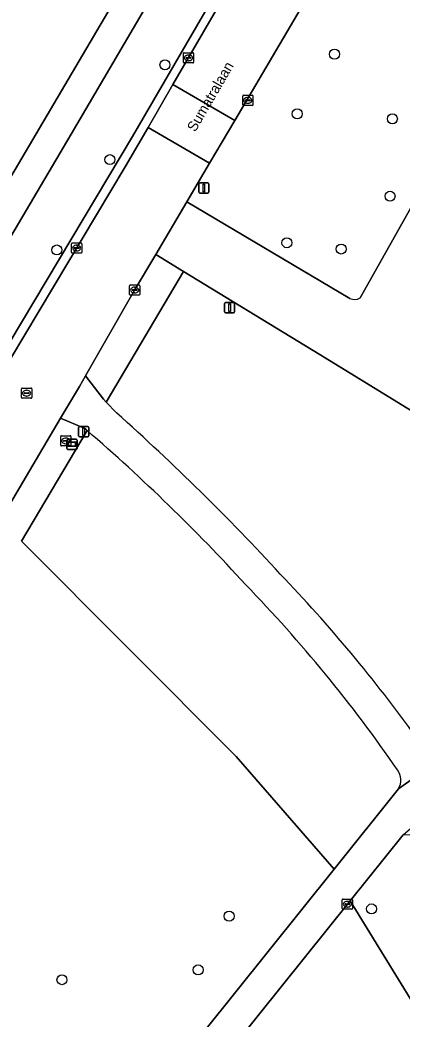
# Model space of a CAD drawing. Extents: x 162417 to 163722, y 384268 to 385417.
# Drawn here: x 162563 to 162600.4, y 384792.3 to 384890.1 of the extents above; entities that cross this region are included whole.
import ezdxf

# ---------------------------------------------------------------- set-up
doc = ezdxf.new("R2010")
doc.units = 0
for name, color, linetype in [('IMGEO_Berm_groen', 7, 'Continuous'), ('IMGEO_Boom', 7, 'Continuous'), ('IMGEO_Brandkraan', 7, 'Continuous'), ('IMGEO_Fietspad_gesloten', 7, 'Continuous'), ('IMGEO_Groenvoorziening', 7, 'Continuous'), ('IMGEO_Kolk', 7, 'Continuous'), ('IMGEO_Lichtmast', 7, 'Continuous'), ('IMGEO_Loofbos', 7, 'Continuous'), ('IMGEO_Openbare_ruimte_label', 7, 'Continuous'), ('IMGEO_Parkeervlak_gesloten', 7, 'Continuous'), ('IMGEO_Rijbaan_lokaal_open', 7, 'Continuous'), ('IMGEO_Rioolput', 7, 'Continuous'), ('IMGEO_Verkeersbordpaal', 7, 'Continuous'), ('IMGEO_Verkeerseiland_open', 7, 'Continuous'), ('IMGEO_Verklikker', 7, 'Continuous'), ('IMGEO_Voetpad_gesloten', 7, 'Continuous')]:
    doc.layers.add(name, color=color, linetype=linetype)

msp = doc.modelspace()

# ---------------------------------------------------------------- linework, layer by layer
at = {"layer": 'IMGEO_Berm_groen'}
for points in [[(162646.158, 385011.686), (162636.511, 384995.272), (162626.239, 384977.745), (162605.301, 384942.481), (162574.943, 384890.8), (162567.991, 384878.959), (162546.279, 384842.21), (162538.301, 384828.127)], [(162512.784, 384784.469), (162517.731, 384790.829), (162522.347, 384797.449), (162531.41, 384811.598), (162533.25, 384810.499), (162574.003, 384878.733), (162603.443, 384929.38), (162645.063, 385000)]]:
    msp.add_lwpolyline(points, dxfattribs=at)
at = {"layer": 'IMGEO_Boom'}
for centre in [(162593.756, 384886.796), (162577.174, 384885.747), (162590.108, 384880.956), (162599.418, 384880.47), (162571.785, 384876.48), (162599.186, 384872.902), (162589.1, 384868.347), (162566.6, 384867.643), (162594.409, 384867.736), (162597.381, 384803.204), (162583.448, 384802.497), (162580.423, 384797.242), (162567.1, 384796.281)]:
    msp.add_circle(centre, 0.489, dxfattribs=at)
at = {"layer": 'IMGEO_Brandkraan'}
for p, q in [((162566.977, 384848.551), (162566.977, 384849.403)), ((162567.052, 384849.477), (162567.904, 384849.477)), ((162567.465, 384849.257), (162567.49, 384849.257)), ((162567.978, 384849.403), (162567.978, 384848.551)), ((162567.904, 384848.477), (162567.052, 384848.477)), ((162567.236, 384848.971), (162567.236, 384848.983)), ((162567.674, 384848.934), (162567.276, 384848.934)), ((162567.279, 384849.02), (162567.677, 384849.02)), ((162567.488, 384848.697), (162567.463, 384848.697)), ((162567.72, 384848.983), (162567.72, 384848.971))]:
    msp.add_line(p, q, dxfattribs=at)
for points in [[(162566.977, 384848.551), (162566.977, 384849.403)], [(162567.052, 384849.477), (162567.904, 384849.477)], [(162567.978, 384849.403), (162567.978, 384848.551)], [(162567.904, 384848.477), (162567.052, 384848.477)]]:
    msp.add_lwpolyline(points, dxfattribs=at)
for centre, radius, start, end in [((162567.054, 384849.401), 0.0765, 91.55205, 178.44795), ((162567.054, 384849.401), 0.0765, 91.55205, 178.44795), ((162567.902, 384849.401), 0.0765, 1.55205, 88.44795), ((162567.902, 384849.401), 0.0765, 1.55205, 88.44795), ((162567.054, 384848.553), 0.0765, 181.55205, 268.44795), ((162567.054, 384848.553), 0.0765, 181.55205, 268.44795), ((162567.276, 384848.98), 0.0403, 85.87752, 175.75265), ((162567.273, 384848.97), 0.0366, 178.93798, 274.71019), ((162567.677, 384848.977), 0.043, 264.86636, 352.45326), ((162567.681, 384848.982), 0.0386, 1.73085, 96.63898), ((162567.902, 384848.553), 0.0765, 271.55205, 358.44795), ((162567.902, 384848.553), 0.0765, 271.55205, 358.44795)]:
    msp.add_arc(centre, radius, start, end, dxfattribs=at)
for centre, major_axis, ratio, start_param, end_param in [((162567.464, 384848.977), (-0.387, 0.002), 0.722429, 4.712389, 7.853982), ((162567.489, 384848.977), (-0.39, 0.002), 0.717154, 1.570796, 4.712389)]:
    msp.add_ellipse(centre, major_axis=major_axis, ratio=ratio, start_param=start_param, end_param=end_param, dxfattribs=at)
at = {"layer": 'IMGEO_Fietspad_gesloten'}
for points in [[(162538.301, 384828.127), (162546.279, 384842.21), (162567.991, 384878.959), (162574.943, 384890.8), (162605.301, 384942.481), (162626.239, 384977.745), (162636.511, 384995.272), (162646.158, 385011.686), (162665.162, 385043.815), (162688.11, 385082.922), (162698.612, 385100.627), (162708.059, 385116.686), (162716.824, 385131.415), (162722.948, 385142.12), (162732.602, 385158.264), (162737.703, 385167.304), (162744.274, 385178.198), (162747.814, 385184.015), (162751.837, 385189.593), (162755.758, 385194.058), (162761.272, 385200.676), (162764.186, 385204.086), (162767.106, 385207.275)], [(162728.189, 385156.751), (162639.731, 385006.611), (162638.556, 385004.617), (162637.018, 385002.006), (162635.965, 385000.219), (162635.836, 385000), (162541.367, 384839.659), (162536.789, 384831.846)]]:
    msp.add_lwpolyline(points, dxfattribs=at)
at = {"layer": 'IMGEO_Groenvoorziening'}
for points in [[(162536.789, 384831.846), (162541.367, 384839.659), (162635.836, 385000)], [(162633.966, 384921.515), (162627.253, 384920.845), (162606.724, 384919.159), (162596.142, 384900.925), (162583.998, 384880.314), (162581.541, 384876.144), (162579.3, 384872.341), (162595.252, 384862.905)], [(162596.252, 384862.955), (162608.361, 384884.447), (162624.176, 384912.71), (162630.141, 384909.345), (162631.465, 384909.747), (162631.987, 384910.232), (162636.105, 384917.629)], [(162593.733, 384807.099), (162584.151, 384818.116), (162563.152, 384839.163), (162569.554, 384849.987), (162569.417, 384850.105), (162569.279, 384850.223), (162566.97, 384851.211), (162540.368, 384806.125), (162542.942, 384804.552), (162541.302, 384801.661), (162539.637, 384798.807), (162533.671, 384788.344), (162529.98, 384781.104), (162527.976, 384776.852), (162526.899, 384773.575), (162525.814, 384770.003)], [(162604.297, 384810.402), (162600.477, 384810.447), (162595.297, 384803.992), (162606.136, 384786.338), (162615.926, 384792.421)], [(162532.879, 384755.269), (162541.11, 384750), (162545.602, 384747.124), (162593.733, 384807.099)], [(162619.678, 384785.416), (162615.926, 384792.421), (162606.136, 384786.338), (162595.297, 384803.992), (162568.435, 384770.521), (162570.041, 384769.255), (162570.101, 384769.331), (162571.485, 384768.241), (162570.384, 384766.843), (162569, 384767.934), (162569.063, 384768.014), (162567.447, 384769.289), (162548.211, 384745.32), (162564.266, 384734.123)]]:
    msp.add_lwpolyline(points, dxfattribs=at)
msp.add_lwpolyline([(162578.998, 384865.545), (162576.291, 384867.199), (162574.209, 384863.722), (162569.407, 384855.341), (162571.149, 384853.057), (162571.438, 384852.752)], close=True, dxfattribs=at)
msp.add_arc((162595.705, 384863.868), 1.064, 244.7926, 300.93221, dxfattribs=at)
at = {"layer": 'IMGEO_Kolk'}
for p, q in [((162578.972, 384886.005), (162578.972, 384886.857)), ((162579.047, 384886.931), (162579.899, 384886.931)), ((162579.231, 384886.425), (162579.231, 384886.437)), ((162579.669, 384886.388), (162579.271, 384886.388)), ((162579.274, 384886.474), (162579.672, 384886.474)), ((162579.46, 384886.711), (162579.485, 384886.711)), ((162579.715, 384886.437), (162579.715, 384886.425)), ((162579.973, 384886.857), (162579.973, 384886.005)), ((162579.899, 384885.931), (162579.047, 384885.931)), ((162579.483, 384886.151), (162579.458, 384886.151)), ((162584.783, 384881.844), (162584.783, 384882.696)), ((162584.858, 384882.77), (162585.71, 384882.77)), ((162585.271, 384882.55), (162585.296, 384882.55)), ((162585.784, 384882.696), (162585.784, 384881.844)), ((162585.71, 384881.77), (162584.858, 384881.77)), ((162585.042, 384882.264), (162585.042, 384882.276)), ((162585.48, 384882.227), (162585.082, 384882.227)), ((162585.085, 384882.313), (162585.483, 384882.313)), ((162585.294, 384881.99), (162585.269, 384881.99)), ((162585.526, 384882.276), (162585.526, 384882.264)), ((162568.037, 384867.406), (162568.037, 384868.258)), ((162568.112, 384868.332), (162568.964, 384868.332)), ((162568.296, 384867.826), (162568.296, 384867.838)), ((162568.734, 384867.789), (162568.336, 384867.789)), ((162568.339, 384867.875), (162568.737, 384867.875)), ((162568.525, 384868.112), (162568.55, 384868.112)), ((162568.78, 384867.838), (162568.78, 384867.826)), ((162569.038, 384868.258), (162569.038, 384867.406)), ((162568.964, 384867.332), (162568.112, 384867.332)), ((162568.548, 384867.552), (162568.523, 384867.552)), ((162573.713, 384863.296), (162573.713, 384864.148)), ((162573.788, 384864.222), (162574.64, 384864.222)), ((162574.201, 384864.002), (162574.226, 384864.002)), ((162574.714, 384864.148), (162574.714, 384863.296)), ((162574.64, 384863.222), (162573.788, 384863.222)), ((162573.972, 384863.716), (162573.972, 384863.728)), ((162574.41, 384863.679), (162574.012, 384863.679)), ((162574.015, 384863.765), (162574.413, 384863.765)), ((162574.224, 384863.442), (162574.199, 384863.442)), ((162574.456, 384863.728), (162574.456, 384863.716)), ((162594.515, 384803.241), (162594.515, 384804.093)), ((162594.59, 384804.167), (162595.442, 384804.167)), ((162594.774, 384803.661), (162594.774, 384803.673)), ((162595.212, 384803.624), (162594.814, 384803.624)), ((162594.817, 384803.71), (162595.215, 384803.71)), ((162595.026, 384803.387), (162595.001, 384803.387)), ((162595.003, 384803.947), (162595.028, 384803.947)), ((162595.258, 384803.673), (162595.258, 384803.661)), ((162595.516, 384804.093), (162595.516, 384803.241)), ((162595.442, 384803.167), (162594.59, 384803.167))]:
    msp.add_line(p, q, dxfattribs=at)
for points in [[(162578.972, 384886.005), (162578.972, 384886.857)], [(162579.047, 384886.931), (162579.899, 384886.931)], [(162579.973, 384886.857), (162579.973, 384886.005)], [(162579.899, 384885.931), (162579.047, 384885.931)], [(162584.783, 384881.844), (162584.783, 384882.696)], [(162584.858, 384882.77), (162585.71, 384882.77)], [(162585.784, 384882.696), (162585.784, 384881.844)], [(162585.71, 384881.77), (162584.858, 384881.77)], [(162568.037, 384867.406), (162568.037, 384868.258)], [(162568.112, 384868.332), (162568.964, 384868.332)], [(162569.038, 384868.258), (162569.038, 384867.406)], [(162568.964, 384867.332), (162568.112, 384867.332)], [(162573.713, 384863.296), (162573.713, 384864.148)], [(162573.788, 384864.222), (162574.64, 384864.222)], [(162574.714, 384864.148), (162574.714, 384863.296)], [(162574.64, 384863.222), (162573.788, 384863.222)], [(162594.515, 384803.241), (162594.515, 384804.093)], [(162594.59, 384804.167), (162595.442, 384804.167)], [(162595.516, 384804.093), (162595.516, 384803.241)], [(162595.442, 384803.167), (162594.59, 384803.167)]]:
    msp.add_lwpolyline(points, dxfattribs=at)
for centre, radius, start, end in [((162579.049, 384886.855), 0.0765, 91.55205, 178.44795), ((162579.049, 384886.855), 0.0765, 91.55205, 178.44795), ((162579.271, 384886.434), 0.0403, 85.87752, 175.75265), ((162579.268, 384886.424), 0.0366, 178.93798, 274.71019), ((162579.672, 384886.431), 0.043, 264.86636, 352.45326), ((162579.676, 384886.436), 0.0386, 1.73085, 96.63898), ((162579.897, 384886.855), 0.0765, 1.55205, 88.44795), ((162579.897, 384886.855), 0.0765, 1.55205, 88.44795), ((162579.049, 384886.007), 0.0765, 181.55205, 268.44795), ((162579.049, 384886.007), 0.0765, 181.55205, 268.44795), ((162579.897, 384886.007), 0.0765, 271.55205, 358.44795), ((162579.897, 384886.007), 0.0765, 271.55205, 358.44795), ((162584.86, 384882.694), 0.0765, 91.55205, 178.44795), ((162584.86, 384882.694), 0.0765, 91.55205, 178.44795), ((162585.708, 384882.694), 0.0765, 1.55205, 88.44795), ((162585.708, 384882.694), 0.0765, 1.55205, 88.44795), ((162584.86, 384881.846), 0.0765, 181.55205, 268.44795), ((162584.86, 384881.846), 0.0765, 181.55205, 268.44795), ((162585.082, 384882.273), 0.0403, 85.87752, 175.75265), ((162585.079, 384882.263), 0.0366, 178.93798, 274.71019), ((162585.483, 384882.27), 0.043, 264.86636, 352.45326), ((162585.487, 384882.275), 0.0386, 1.73085, 96.63898), ((162585.708, 384881.846), 0.0765, 271.55205, 358.44795), ((162585.708, 384881.846), 0.0765, 271.55205, 358.44795), ((162568.114, 384868.256), 0.0765, 91.55205, 178.44795), ((162568.114, 384868.256), 0.0765, 91.55205, 178.44795), ((162568.336, 384867.835), 0.0403, 85.87752, 175.75265), ((162568.333, 384867.825), 0.0366, 178.93798, 274.71019), ((162568.737, 384867.832), 0.043, 264.86636, 352.45326), ((162568.741, 384867.837), 0.0386, 1.73085, 96.63898), ((162568.962, 384868.256), 0.0765, 1.55205, 88.44795), ((162568.962, 384868.256), 0.0765, 1.55205, 88.44795), ((162568.114, 384867.408), 0.0765, 181.55205, 268.44795), ((162568.114, 384867.408), 0.0765, 181.55205, 268.44795), ((162568.962, 384867.408), 0.0765, 271.55205, 358.44795), ((162568.962, 384867.408), 0.0765, 271.55205, 358.44795), ((162573.79, 384864.146), 0.0765, 91.55205, 178.44795), ((162573.79, 384864.146), 0.0765, 91.55205, 178.44795), ((162574.638, 384864.146), 0.0765, 1.55205, 88.44795), ((162574.638, 384864.146), 0.0765, 1.55205, 88.44795), ((162573.79, 384863.298), 0.0765, 181.55205, 268.44795), ((162573.79, 384863.298), 0.0765, 181.55205, 268.44795), ((162574.012, 384863.725), 0.0403, 85.87752, 175.75265), ((162574.009, 384863.715), 0.0366, 178.93798, 274.71019), ((162574.413, 384863.722), 0.043, 264.86636, 352.45326), ((162574.417, 384863.727), 0.0386, 1.73085, 96.63898), ((162574.638, 384863.298), 0.0765, 271.55205, 358.44795), ((162574.638, 384863.298), 0.0765, 271.55205, 358.44795), ((162594.592, 384804.091), 0.0765, 91.55205, 178.44795), ((162594.592, 384804.091), 0.0765, 91.55205, 178.44795), ((162594.814, 384803.67), 0.0403, 85.87752, 175.75265), ((162594.811, 384803.66), 0.0366, 178.93798, 274.71019), ((162595.215, 384803.667), 0.043, 264.86636, 352.45326), ((162595.219, 384803.672), 0.0386, 1.73085, 96.63898), ((162595.44, 384804.091), 0.0765, 1.55205, 88.44795), ((162595.44, 384804.091), 0.0765, 1.55205, 88.44795), ((162594.592, 384803.243), 0.0765, 181.55205, 268.44795), ((162594.592, 384803.243), 0.0765, 181.55205, 268.44795), ((162595.44, 384803.243), 0.0765, 271.55205, 358.44795), ((162595.44, 384803.243), 0.0765, 271.55205, 358.44795)]:
    msp.add_arc(centre, radius, start, end, dxfattribs=at)
for centre, major_axis, ratio, start_param, end_param in [((162579.459, 384886.431), (-0.387, 0.002), 0.722429, 4.712389, 7.853982), ((162579.484, 384886.431), (-0.39, 0.002), 0.717154, 1.570796, 4.712389), ((162585.27, 384882.27), (-0.387, 0.002), 0.722429, 4.712389, 7.853982), ((162585.295, 384882.27), (-0.39, 0.002), 0.717154, 1.570796, 4.712389), ((162568.524, 384867.832), (-0.387, 0.002), 0.722429, 4.712389, 7.853982), ((162568.549, 384867.832), (-0.39, 0.002), 0.717154, 1.570796, 4.712389), ((162574.2, 384863.722), (-0.387, 0.002), 0.722429, 4.712389, 7.853982), ((162574.225, 384863.722), (-0.39, 0.002), 0.717154, 1.570796, 4.712389), ((162595.002, 384803.667), (-0.387, 0.002), 0.722429, 4.712389, 7.853982), ((162595.027, 384803.667), (-0.39, 0.002), 0.717154, 1.570796, 4.712389)]:
    msp.add_ellipse(centre, major_axis=major_axis, ratio=ratio, start_param=start_param, end_param=end_param, dxfattribs=at)
at = {"layer": 'IMGEO_Lichtmast'}
for p, q in [((162580.479, 384873.302), (162580.479, 384874.102)), ((162580.479, 384874.102), (162580.479, 384873.302)), ((162580.579, 384874.202), (162581.369, 384874.202)), ((162581.369, 384874.202), (162580.579, 384874.202)), ((162581.469, 384874.102), (162581.469, 384873.302)), ((162581.469, 384873.302), (162581.469, 384874.102)), ((162581.369, 384873.202), (162580.579, 384873.202)), ((162580.579, 384873.202), (162581.369, 384873.202))]:
    msp.add_line(p, q, dxfattribs=at)
msp.add_lwpolyline([(162580.899, 384874.077), (162581.049, 384874.077), (162581.049, 384873.327), (162580.899, 384873.327), (162580.899, 384874.077)], dxfattribs=at)
for centre, start, end in [((162580.579, 384874.102), 90, 180), ((162580.579, 384874.102), 90, 180), ((162581.369, 384874.102), 0, 90), ((162581.369, 384874.102), 360, 90), ((162580.579, 384873.302), 180, 270), ((162580.579, 384873.302), 180, 270), ((162581.369, 384873.302), 270, 0), ((162581.369, 384873.302), 270, 0)]:
    msp.add_arc(centre, 0.1, start, end, dxfattribs=at)
at = {"layer": 'IMGEO_Loofbos'}
for points in [[(162609.827, 384847.286), (162609.567, 384846.838), (162596.309, 384854.964), (162592.241, 384857.45), (162578.998, 384865.545), (162571.438, 384852.752), (162572.419, 384851.714)], [(162569.554, 384849.987), (162563.152, 384839.163), (162584.151, 384818.116), (162593.733, 384807.099), (162600.029, 384814.944)]]:
    msp.add_lwpolyline(points, dxfattribs=at)
for centre, radius, start, end in [((162426.197, 384687.011), 220.245, 42.54989, 48.40153), ((162451.895, 384713.407), 180.271, 42.38212, 49.25613), ((162483.277, 384734.796), 145.921, 35.72297, 43.88394), ((162482.506, 384735.63), 142.743, 34.6554, 44.07578), ((162598.455, 384815.785), 1.784, 331.86516, 34.61424)]:
    msp.add_arc(centre, radius, start, end, dxfattribs=at)
at = {"layer": 'IMGEO_Parkeervlak_gesloten'}
for points in [[(162642.404, 384902.325), (162636.868, 384905.565), (162630.141, 384909.345), (162624.176, 384912.71), (162608.361, 384884.447), (162596.252, 384862.955)], [(162595.252, 384862.905), (162579.3, 384872.341), (162576.291, 384867.199), (162578.998, 384865.545), (162592.241, 384857.45), (162596.309, 384854.964), (162609.567, 384846.838), (162609.827, 384847.286), (162612.071, 384851.147), (162612.197, 384851.361), (162625.393, 384873.785), (162642.404, 384902.325)]]:
    msp.add_lwpolyline(points, dxfattribs=at)
msp.add_arc((162595.705, 384863.868), 1.064, 244.7926, 300.93221, dxfattribs=at)
at = {"layer": 'IMGEO_Rijbaan_lokaal_open'}
for points in [[(162577.959, 384883.818), (162583.998, 384880.314), (162596.142, 384900.925), (162606.724, 384919.159), (162611.145, 384926.587), (162654.361, 385000), (162655.133, 385001.311), (162659.828, 385009.341), (162691.301, 385062.57), (162692.946, 385065.327), (162693.28, 385065.893), (162687.012, 385069.599), (162646.005, 385000), (162607.006, 384933.97), (162586.721, 384898.921)], [(162575.53, 384879.632), (162581.541, 384876.144), (162583.998, 384880.314), (162577.959, 384883.818)]]:
    msp.add_lwpolyline(points, close=True, dxfattribs=at)
msp.add_lwpolyline([(162529.821, 384787.499), (162530.911, 384789.535), (162534.987, 384797.022), (162540.368, 384806.125), (162566.97, 384851.211), (162568.815, 384854.307), (162569.407, 384855.341), (162574.209, 384863.722), (162576.291, 384867.199), (162579.3, 384872.341), (162581.541, 384876.144), (162575.53, 384879.632), (162573.285, 384875.763), (162533.977, 384810.065), (162532.771, 384808.049), (162523.657, 384794.437), (162522.365, 384792.536), (162521.094, 384790.707), (162519.826, 384788.918), (162513.62, 384780.863)], dxfattribs=at)
at = {"layer": 'IMGEO_Rioolput'}
for p, q in [((162563.214, 384854.142), (162564.066, 384854.142)), ((162563.139, 384853.216), (162563.139, 384854.068)), ((162564.066, 384853.142), (162563.214, 384853.142)), ((162563.398, 384853.636), (162563.398, 384853.648)), ((162563.836, 384853.599), (162563.438, 384853.599)), ((162563.441, 384853.685), (162563.839, 384853.685)), ((162563.65, 384853.362), (162563.625, 384853.362)), ((162563.627, 384853.922), (162563.652, 384853.922)), ((162563.882, 384853.648), (162563.882, 384853.636)), ((162564.14, 384854.068), (162564.14, 384853.216))]:
    msp.add_line(p, q, dxfattribs=at)
for points in [[(162563.214, 384854.142), (162564.066, 384854.142)], [(162563.139, 384853.216), (162563.139, 384854.068)], [(162564.066, 384853.142), (162563.214, 384853.142)], [(162564.14, 384854.068), (162564.14, 384853.216)]]:
    msp.add_lwpolyline(points, dxfattribs=at)
for centre, radius, start, end in [((162563.216, 384854.066), 0.0765, 91.55205, 178.44795), ((162563.216, 384854.066), 0.0765, 91.55205, 178.44795), ((162564.064, 384854.066), 0.0765, 1.55205, 88.44795), ((162564.064, 384854.066), 0.0765, 1.55205, 88.44795), ((162563.216, 384853.218), 0.0765, 181.55205, 268.44795), ((162563.216, 384853.218), 0.0765, 181.55205, 268.44795), ((162563.438, 384853.645), 0.0403, 85.87752, 175.75265), ((162563.435, 384853.635), 0.0366, 178.93798, 274.71019), ((162563.839, 384853.642), 0.043, 264.86636, 352.45326), ((162563.843, 384853.647), 0.0386, 1.73085, 96.63898), ((162564.064, 384853.218), 0.0765, 271.55205, 358.44795), ((162564.064, 384853.218), 0.0765, 271.55205, 358.44795)]:
    msp.add_arc(centre, radius, start, end, dxfattribs=at)
for centre, major_axis, ratio, start_param, end_param in [((162563.626, 384853.642), (-0.387, 0.002), 0.722429, 4.712389, 7.853982), ((162563.651, 384853.642), (-0.39, 0.002), 0.717154, 1.570796, 4.712389)]:
    msp.add_ellipse(centre, major_axis=major_axis, ratio=ratio, start_param=start_param, end_param=end_param, dxfattribs=at)
at = {"layer": 'IMGEO_Verkeersbordpaal'}
for p, q in [((162583, 384861.606), (162583, 384862.406)), ((162583, 384862.406), (162583, 384861.606)), ((162583.1, 384862.506), (162583.89, 384862.506)), ((162583.89, 384862.506), (162583.1, 384862.506)), ((162583.99, 384862.406), (162583.99, 384861.606)), ((162583.99, 384861.606), (162583.99, 384862.406)), ((162583.89, 384861.506), (162583.1, 384861.506)), ((162583.1, 384861.506), (162583.89, 384861.506)), ((162568.727, 384849.484), (162568.727, 384850.284)), ((162568.727, 384850.284), (162568.727, 384849.484)), ((162568.827, 384850.384), (162569.617, 384850.384)), ((162569.617, 384850.384), (162568.827, 384850.384)), ((162569.717, 384850.284), (162569.717, 384849.484)), ((162569.717, 384849.484), (162569.717, 384850.284)), ((162569.617, 384849.384), (162568.827, 384849.384)), ((162568.827, 384849.384), (162569.617, 384849.384))]:
    msp.add_line(p, q, dxfattribs=at)
for points in [[(162583.42, 384862.381), (162583.57, 384862.381), (162583.57, 384861.631), (162583.42, 384861.631), (162583.42, 384862.381)], [(162569.147, 384850.259), (162569.297, 384850.259), (162569.297, 384849.509), (162569.147, 384849.509), (162569.147, 384850.259)]]:
    msp.add_lwpolyline(points, dxfattribs=at)
for centre, start, end in [((162583.1, 384862.406), 90, 180), ((162583.1, 384862.406), 90, 180), ((162583.89, 384862.406), 0, 90), ((162583.89, 384862.406), 360, 90), ((162583.1, 384861.606), 180, 270), ((162583.1, 384861.606), 180, 270), ((162583.89, 384861.606), 270, 0), ((162583.89, 384861.606), 270, 0), ((162568.827, 384850.284), 90, 180), ((162568.827, 384850.284), 90, 180), ((162569.617, 384850.284), 0, 90), ((162569.617, 384850.284), 360, 90), ((162568.827, 384849.484), 180, 270), ((162568.827, 384849.484), 180, 270), ((162569.617, 384849.484), 270, 0), ((162569.617, 384849.484), 270, 0)]:
    msp.add_arc(centre, 0.1, start, end, dxfattribs=at)
at = {"layer": 'IMGEO_Verkeerseiland_open'}
msp.add_lwpolyline([(162767.106, 385207.275), (162766.836, 385206.78), (162762.895, 385199.938), (162645.063, 385000), (162603.443, 384929.38), (162574.003, 384878.733), (162533.25, 384810.499), (162533.977, 384810.065), (162573.285, 384875.763), (162575.53, 384879.632), (162577.959, 384883.818), (162586.721, 384898.921), (162607.006, 384933.97), (162646.005, 385000)], dxfattribs=at)
at = {"layer": 'IMGEO_Verklikker'}
for p, q in [((162567.586, 384848.246), (162567.586, 384849.046)), ((162567.586, 384849.046), (162567.586, 384848.246)), ((162567.686, 384849.146), (162568.476, 384849.146)), ((162568.476, 384849.146), (162567.686, 384849.146)), ((162568.576, 384849.046), (162568.576, 384848.246)), ((162568.576, 384848.246), (162568.576, 384849.046)), ((162568.476, 384848.146), (162567.686, 384848.146)), ((162567.686, 384848.146), (162568.476, 384848.146))]:
    msp.add_line(p, q, dxfattribs=at)
for points in [[(162567.687, 384848.878), (162568.475, 384848.878), (162568.475, 384848.414), (162567.687, 384848.414), (162567.687, 384848.878)], [(162567.752, 384848.813), (162567.752, 384848.479), (162568.41, 384848.479), (162568.41, 384848.813), (162567.752, 384848.813)]]:
    msp.add_lwpolyline(points, dxfattribs=at)
for centre, start, end in [((162567.686, 384849.046), 90, 180), ((162567.686, 384849.046), 90, 180), ((162567.686, 384848.246), 180, 270), ((162567.686, 384848.246), 180, 270), ((162568.476, 384849.046), 0, 90), ((162568.476, 384849.046), 360, 90), ((162568.476, 384848.246), 270, 0), ((162568.476, 384848.246), 270, 0)]:
    msp.add_arc(centre, 0.1, start, end, dxfattribs=at)
at = {"layer": 'IMGEO_Voetpad_gesloten'}
for points in [[(162660.098, 384866.636), (162653.854, 384861.044), (162618.576, 384830.021), (162618.485, 384829.944), (162613.276, 384825.51), (162605.329, 384818.744), (162600.029, 384814.944), (162593.733, 384807.099), (162545.602, 384747.124), (162548.211, 384745.32), (162567.447, 384769.289), (162568.435, 384770.521), (162595.297, 384803.992), (162600.477, 384810.447), (162606.892, 384815.961)], [(162572.419, 384851.714), (162571.438, 384852.752), (162571.149, 384853.057), (162569.407, 384855.341), (162568.815, 384854.307), (162566.97, 384851.211), (162569.279, 384850.223), (162569.417, 384850.105), (162569.554, 384849.987)], [(162600.029, 384814.944), (162605.329, 384818.744)]]:
    msp.add_lwpolyline(points, dxfattribs=at)
for centre, radius, start, end in [((162426.197, 384687.011), 220.245, 42.54989, 48.40153), ((162451.895, 384713.407), 180.271, 42.38212, 49.25613), ((162483.277, 384734.796), 145.921, 35.72297, 43.88394), ((162482.506, 384735.63), 142.743, 34.6554, 44.07578), ((162598.455, 384815.785), 1.784, 331.86516, 34.61424)]:
    msp.add_arc(centre, radius, start, end, dxfattribs=at)

# ---------------------------------------------------------------- texts
at = {"layer": 'IMGEO_Openbare_ruimte_label'}
msp.add_text('Sumatralaan', height=1, rotation=59.8714, dxfattribs=at).set_placement((162580.133, 384879.119))

doc.saveas('drawing.dxf')
